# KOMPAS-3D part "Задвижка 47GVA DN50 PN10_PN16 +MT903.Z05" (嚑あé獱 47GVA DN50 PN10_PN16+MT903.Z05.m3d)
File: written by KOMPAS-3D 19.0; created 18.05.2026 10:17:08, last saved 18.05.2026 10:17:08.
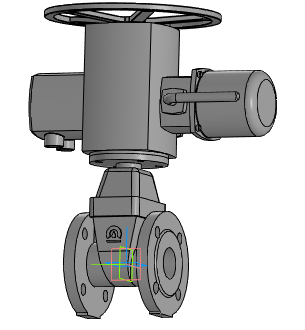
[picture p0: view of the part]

Document properties: Автор: Энергия; Полное имя файла: ..\Задвижка 47GVA DN50_DN1000+MT903.Z\Задвижка 47GVA DN50 PN10_PN16+MT903.Z05.a3d

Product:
- Part/product: Задвижка 47GVA DN50 PN10_PN16 +MT903.Z05
    Масса: 65.606
  - Body: Электропривод MT903.Z05-15
      Масса: 49.8062
  - Body: Задвижка 47GVA DN50 PN10_PN16 без исполн. мех.
      Масса: 15.7998

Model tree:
1. Операция без истории:1
2. Операция без истории:2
